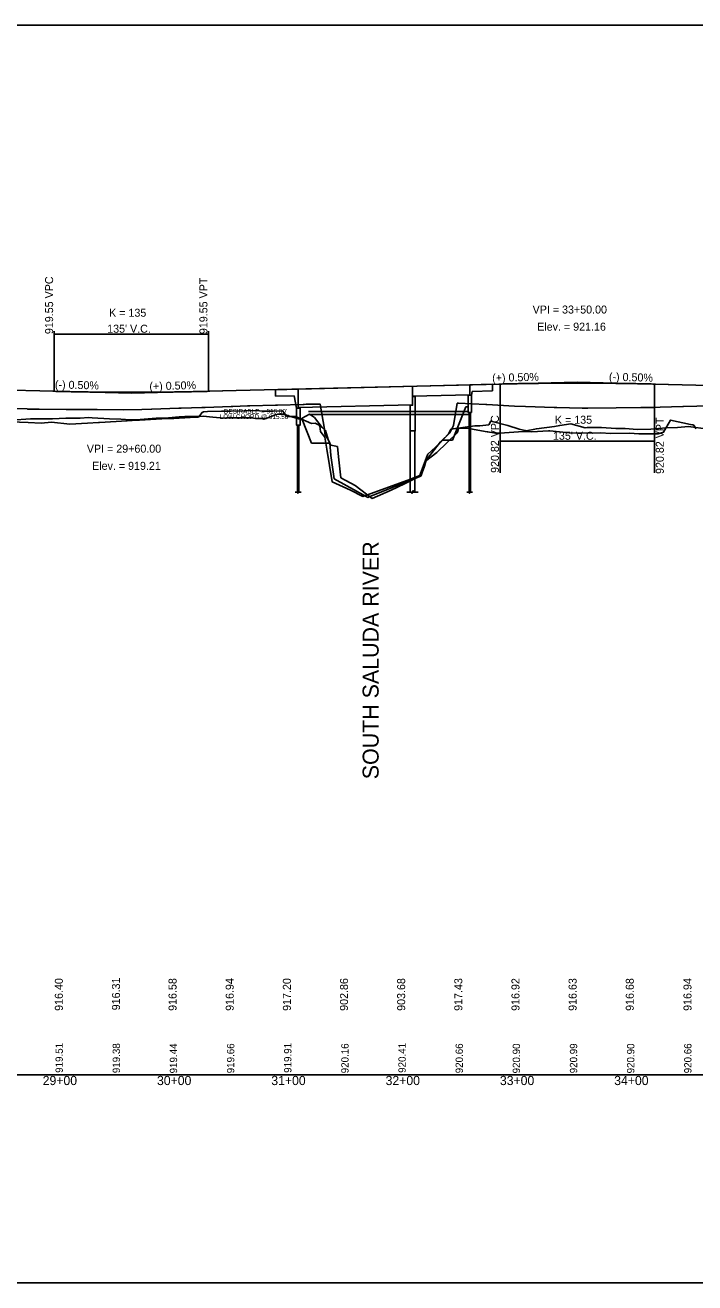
# Model space of a CAD drawing. Extents: x 1538426 to 1542651, y 1162537 to 1163637.
# Drawn here: x 1540293 to 1540879, y 1162537 to 1163637 of the extents above; entities that cross this region are included whole.
import ezdxf

# ---------------------------------------------------------------- set-up
doc = ezdxf.new("R2010")
doc.units = 0
for name, color, linetype in [('BR_CONCRETE', 7, 'Continuous'), ('BR_EXIST_GROUND_LT', 7, 'Continuous'), ('BR_EXIST_GROUND_RT', 7, 'Continuous'), ('BR_GROUND LINES', 7, 'Continuous'), ('BR_USER NOTES', 7, 'Continuous'), ('Default', 7, 'Continuous'), ('RD_DDB_GradeTX', 7, 'Continuous'), ('RD_DDB_Profile_EX', 7, 'Continuous'), ('RD_DDB_Profile_Lbl', 7, 'Continuous'), ('RD_DDB_Profile_PR', 7, 'Continuous'), ('RD_DDB_StaTX', 7, 'Continuous'), ('RD_DDB_StripGrade', 7, 'Continuous'), ('RD_DDB_VCLbl', 7, 'Continuous'), ('RD_HC_Data_Tic', 7, 'Continuous'), ('RD_SHT_ShtClip', 7, 'Continuous'), ('RD_SHT_TX', 7, 'Continuous')]:
    doc.layers.add(name, color=color, linetype=linetype)

msp = doc.modelspace()

# ---------------------------------------------------------------- linework, layer by layer
at = {"layer": 'BR_CONCRETE'}
for p, q in [((1540511.9, 1163317.9), (1540531.9, 1163318.4)), ((1540511.9, 1163312.1), (1540511.9, 1163317.9)), ((1540531.9, 1163318.4), (1540681.9, 1163322.2)), ((1540531.9, 1163301.8), (1540531.9, 1163318.4)), ((1540631.9, 1163320.9), (1540631.9, 1163304.7)), ((1540681.9, 1163322.2), (1540701.9, 1163322.7)), ((1540681.9, 1163322.2), (1540681.9, 1163313)), ((1540683.4, 1163313), (1540684.1, 1163316.4)), ((1540684.1, 1163316.4), (1540701.9, 1163316.8)), ((1540511.9, 1163312.1), (1540528.3, 1163312.5)), ((1540530.4, 1163301.8), (1540528.3, 1163312.5)), ((1540631.9, 1163312.2), (1540681.9, 1163313.4)), ((1540531.9, 1163302.2), (1540631.9, 1163304.7)), ((1540681.3, 1163298), (1540681.3, 1163228.4)), ((1540682.5, 1163298), (1540682.5, 1163228.4)), ((1540531.3, 1163286.8), (1540531.3, 1163228.4)), ((1540532.5, 1163286.8), (1540532.5, 1163228.4)), ((1540629.9, 1163228.4), (1540629.9, 1163281.8)), ((1540633.9, 1163228.4), (1540633.9, 1163281.8))]:
    msp.add_line(p, q, dxfattribs=at)
for points in [[(1540629.7, 1163304.3), (1540631.9, 1163304.3), (1540631.9, 1163311.8), (1540634.2, 1163311.8), (1540634.2, 1163281.8), (1540629.7, 1163281.8)], [(1540683.4, 1163313), (1540680.4, 1163313), (1540680.4, 1163298), (1540683.4, 1163298)], [(1540530.4, 1163301.8), (1540533.4, 1163301.8), (1540533.4, 1163286.8), (1540530.4, 1163286.8)]]:
    msp.add_lwpolyline(points, close=True, dxfattribs=at)
for points in [[(1540529.3, 1163228.4), (1540531.6, 1163228.4), (1540531.6, 1163227.2), (1540532.2, 1163229.6), (1540532.3, 1163228.4), (1540534.4, 1163228.4)], [(1540626.9, 1163228.4), (1540631.3, 1163228.4), (1540631.3, 1163227.2), (1540632.5, 1163229.6), (1540632.5, 1163228.4), (1540636.8, 1163228.4)], [(1540679.3, 1163228.4), (1540681.5, 1163228.4), (1540681.6, 1163227.2), (1540682.1, 1163229.6), (1540682.3, 1163228.4), (1540684.4, 1163228.4)]]:
    msp.add_lwpolyline(points, dxfattribs=at)
at = {"layer": 'BR_EXIST_GROUND_LT'}
msp.add_lwpolyline([(1540280.9, 1163291.3), (1540297.5, 1163292.5), (1540298.7, 1163292.5), (1540311.8, 1163292.3), (1540316.8, 1163292.5), (1540328.6, 1163293.1), (1540341.2, 1163293), (1540348.5, 1163293.5), (1540351.7, 1163293.4), (1540366.8, 1163292.4), (1540376.6, 1163292.1), (1540385, 1163291.5), (1540390.1, 1163291.4), (1540407.7, 1163292.9), (1540415, 1163293.1), (1540427.8, 1163294.3), (1540432.6, 1163294.4), (1540448.8, 1163294.8), (1540457.2, 1163293.9), (1540466.7, 1163293), (1540469.1, 1163293.2), (1540491.5, 1163293.2), (1540494.4, 1163292.7), (1540503.9, 1163292.6), (1540511.8, 1163295.8), (1540515, 1163296.5), (1540518.3, 1163296.6), (1540534.2, 1163291.9), (1540534.6, 1163291.9), (1540535.4, 1163293), (1540541.6, 1163296.4), (1540546, 1163293.6), (1540552.9, 1163284.7), (1540555.8, 1163282.2), (1540558.3, 1163273.4), (1540560.3, 1163269.5), (1540566.1, 1163268.2), (1540567, 1163259.1), (1540569.2, 1163240.9), (1540581.8, 1163234.1), (1540596.6, 1163222.8), (1540613.3, 1163230), (1540624.9, 1163235.7), (1540639.4, 1163242.7), (1540643.3, 1163255.3), (1540653, 1163263.1), (1540670.9, 1163280.2), (1540671.4, 1163281.4), (1540672.1, 1163284), (1540679.5, 1163284.3), (1540697, 1163281.1), (1540697.5, 1163281.1), (1540704.6, 1163279.8), (1540708.3, 1163279.8), (1540728.6, 1163281.2), (1540736.1, 1163281.1), (1540750.7, 1163282), (1540752, 1163282), (1540769, 1163280.2), (1540776.9, 1163280), (1540778.5, 1163279.8), (1540779.9, 1163279.8), (1540796.5, 1163280.2), (1540804.9, 1163279.5), (1540821.8, 1163279.9), (1540829.8, 1163279.3), (1540831.7, 1163279.3), (1540846.7, 1163279.3), (1540851.5, 1163280.6), (1540857.5, 1163291.3), (1540875, 1163287.5), (1540877.2, 1163287.3), (1540878.1, 1163286.7), (1540879.7, 1163283.6)], dxfattribs=at)
at = {"layer": 'BR_EXIST_GROUND_RT'}
msp.add_lwpolyline([(1540280.3, 1163289.7), (1540295.7, 1163289.1), (1540306.9, 1163288.6), (1540316.1, 1163289.6), (1540332.1, 1163287.8), (1540347.4, 1163288.7), (1540357.1, 1163289.3), (1540358, 1163289.3), (1540382.1, 1163290.7), (1540391.1, 1163291.3), (1540392.9, 1163291.3), (1540412.4, 1163292.3), (1540417.9, 1163292.6), (1540423, 1163292.8), (1540442.3, 1163293.8), (1540444.5, 1163293.9), (1540447.7, 1163298), (1540449, 1163298.6), (1540452.5, 1163298.8), (1540464.6, 1163299), (1540465.8, 1163299), (1540473.2, 1163299.2), (1540495.5, 1163299.7), (1540500.3, 1163299.1), (1540509.9, 1163299.1), (1540518, 1163299.5), (1540519.6, 1163297.8), (1540522, 1163294.5), (1540529.4, 1163294.5), (1540543.4, 1163288.4), (1540546.6, 1163288.7), (1540550.3, 1163286.9), (1540550.8, 1163286), (1540551.2, 1163281.4), (1540551.8, 1163280.5), (1540555.2, 1163276.3), (1540556.8, 1163266), (1540561.6, 1163237.2), (1540577.6, 1163230.1), (1540588.5, 1163224.6), (1540627.7, 1163238.9), (1540638.2, 1163242.8), (1540638.7, 1163244.7), (1540644.8, 1163261), (1540645.3, 1163261.4), (1540655.4, 1163270.8), (1540663.4, 1163279.4), (1540664.6, 1163281.6), (1540665.4, 1163283.3), (1540686.4, 1163286.2), (1540690.7, 1163286.2), (1540698.6, 1163287.1), (1540700.3, 1163290.4), (1540715.1, 1163286.6), (1540725, 1163283.5), (1540730.3, 1163282.2), (1540731.4, 1163281.8), (1540740.3, 1163283.7), (1540756, 1163285.6), (1540760.6, 1163286.7), (1540770.2, 1163287.9), (1540782.8, 1163284.6), (1540784.6, 1163284.7), (1540797.2, 1163284.9), (1540809.7, 1163283.9), (1540818, 1163284), (1540828.4, 1163283.2), (1540840.3, 1163283.3), (1540853.6, 1163284.5), (1540863.7, 1163284.7), (1540873.3, 1163285.6), (1540890.5, 1163283.5)], dxfattribs=at)
at = {"layer": 'BR_GROUND LINES'}
for p, q in [((1540678.4, 1163303), (1540666.7, 1163273.7)), ((1540666.7, 1163273.7), (1540678.4, 1163303)), ((1540680.4, 1163303), (1540678.4, 1163303)), ((1540678.4, 1163303), (1540680.4, 1163303)), ((1540533.4, 1163291.8), (1540535.4, 1163291.8)), ((1540533.4, 1163291.7), (1540535.4, 1163291.8)), ((1540535.4, 1163291.8), (1540543.6, 1163271.2)), ((1540535.4, 1163291.8), (1540543.6, 1163271.2)), ((1540666.7, 1163273.7), (1540657.7, 1163273.7)), ((1540543.6, 1163271.2), (1540559.6, 1163271.2))]:
    msp.add_line(p, q, dxfattribs=at)
at = {"layer": 'BR_USER NOTES'}
for p, q in [((1540540.9, 1163298.7), (1540680.9, 1163298.7)), ((1540540.9, 1163296.2), (1540680.9, 1163296.2))]:
    msp.add_line(p, q, dxfattribs=at)
at = {"layer": 'Default'}
msp.add_line((1540701.9, 1163322.7), (1540701.9, 1163316.8), dxfattribs=at)
at = {"layer": 'RD_DDB_GradeTX'}
for p, q in [((1540305.9, 1163316.8), (1540385.9, 1163314.8)), ((1540465.9, 1163316.8), (1540385.9, 1163314.8)), ((1540695.9, 1163322.5), (1540775.9, 1163324.5)), ((1540855.9, 1163322.5), (1540775.9, 1163324.5))]:
    msp.add_line(p, q, dxfattribs=at)
at = {"layer": 'RD_DDB_Profile_EX'}
msp.add_lwpolyline([(1540270.5, 1163301.5), (1540294.6, 1163301.1), (1540295.1, 1163301), (1540303.7, 1163300.9), (1540305.3, 1163300.9), (1540328.7, 1163300.7), (1540329.6, 1163300.7), (1540353.8, 1163300.5), (1540356, 1163300.5), (1540378.8, 1163300.2), (1540395.1, 1163300.7), (1540403.4, 1163301), (1540403.8, 1163301), (1540427.4, 1163301.7), (1540428.8, 1163301.7), (1540429.4, 1163301.7), (1540447.5, 1163302.2), (1540448.2, 1163302.3), (1540450.4, 1163302.3), (1540473.2, 1163303.3), (1540474.5, 1163303.3), (1540487.5, 1163303.9), (1540489.5, 1163303.9), (1540512, 1163304.4), (1540513.7, 1163304.5), (1540536.3, 1163304.9), (1540537, 1163305), (1540538.8, 1163305.1), (1540551, 1163305.3), (1540554.8, 1163283.5), (1540555.1, 1163279.2), (1540556.1, 1163277.7), (1540559.6, 1163271.4), (1540560.5, 1163260.4), (1540563.3, 1163240), (1540591.3, 1163224.5), (1540592.2, 1163224), (1540592.6, 1163223.7), (1540594.4, 1163224.5), (1540639.1, 1163242.4), (1540642.4, 1163251.1), (1540643.9, 1163256.4), (1540656.2, 1163272.3), (1540664.4, 1163280.1), (1540667.8, 1163286.7), (1540670.9, 1163306.1), (1540672, 1163306.1), (1540695.9, 1163304.9), (1540696.8, 1163304.8), (1540721.1, 1163303.6), (1540730.7, 1163303.1), (1540755.7, 1163302.4), (1540758.2, 1163302.3), (1540780.3, 1163301.7), (1540780.7, 1163301.7), (1540785.1, 1163301.6), (1540810.1, 1163301.9), (1540831.5, 1163302.2), (1540835.1, 1163302.3), (1540843.9, 1163302.4), (1540848.4, 1163302.5), (1540868.3, 1163303.2), (1540868.9, 1163303.2), (1540892.3, 1163303.9)], dxfattribs=at)
at = {"layer": 'RD_DDB_Profile_PR'}
for p, q in [((1540203.4, 1163319.3), (1540318.4, 1163316.5)), ((1540453.4, 1163316.5), (1540708.4, 1163322.8)), ((1540843.4, 1163322.8), (1541058.4, 1163317.5))]:
    msp.add_line(p, q, dxfattribs=at)
for points in [[(1540318.4, 1163316.5), (1540321.1, 1163316.4), (1540323.8, 1163316.3), (1540326.5, 1163316.3), (1540329.2, 1163316.2), (1540331.9, 1163316.2), (1540334.6, 1163316.1), (1540337.3, 1163316.1), (1540340, 1163316), (1540342.7, 1163316), (1540345.4, 1163315.9), (1540348.1, 1163315.9), (1540350.8, 1163315.8), (1540353.5, 1163315.8), (1540356.2, 1163315.8), (1540358.9, 1163315.7), (1540361.6, 1163315.7), (1540364.3, 1163315.7), (1540367, 1163315.7), (1540369.7, 1163315.7), (1540372.4, 1163315.6), (1540375.1, 1163315.6), (1540377.8, 1163315.6), (1540380.5, 1163315.6), (1540383.2, 1163315.6), (1540385.9, 1163315.6), (1540388.6, 1163315.6), (1540391.3, 1163315.6), (1540394, 1163315.6), (1540396.7, 1163315.6), (1540399.4, 1163315.6), (1540402.1, 1163315.7), (1540404.8, 1163315.7), (1540407.5, 1163315.7), (1540410.2, 1163315.7), (1540412.9, 1163315.7), (1540415.6, 1163315.8), (1540418.3, 1163315.8), (1540421, 1163315.8), (1540423.7, 1163315.9), (1540426.4, 1163315.9), (1540429.1, 1163316), (1540431.8, 1163316), (1540434.5, 1163316.1), (1540437.2, 1163316.1), (1540439.9, 1163316.2), (1540442.6, 1163316.2), (1540445.3, 1163316.3), (1540448, 1163316.3), (1540450.7, 1163316.4), (1540453.4, 1163316.5)], [(1540708.4, 1163322.8), (1540711.1, 1163322.9), (1540713.8, 1163323), (1540716.5, 1163323), (1540719.2, 1163323.1), (1540721.9, 1163323.1), (1540724.6, 1163323.2), (1540727.3, 1163323.2), (1540730, 1163323.3), (1540732.7, 1163323.3), (1540735.4, 1163323.4), (1540738.1, 1163323.4), (1540740.8, 1163323.4), (1540743.5, 1163323.5), (1540746.2, 1163323.5), (1540748.9, 1163323.5), (1540751.6, 1163323.6), (1540754.3, 1163323.6), (1540757, 1163323.6), (1540759.7, 1163323.6), (1540762.4, 1163323.6), (1540765.1, 1163323.7), (1540767.8, 1163323.7), (1540770.5, 1163323.7), (1540773.2, 1163323.7), (1540775.9, 1163323.7), (1540778.6, 1163323.7), (1540781.3, 1163323.7), (1540784, 1163323.7), (1540786.7, 1163323.7), (1540789.4, 1163323.6), (1540792.1, 1163323.6), (1540794.8, 1163323.6), (1540797.5, 1163323.6), (1540800.2, 1163323.6), (1540802.9, 1163323.5), (1540805.6, 1163323.5), (1540808.3, 1163323.5), (1540811, 1163323.4), (1540813.7, 1163323.4), (1540816.4, 1163323.4), (1540819.1, 1163323.3), (1540821.8, 1163323.3), (1540824.5, 1163323.2), (1540827.2, 1163323.2), (1540829.9, 1163323.1), (1540832.6, 1163323.1), (1540835.3, 1163323), (1540838, 1163323), (1540840.7, 1163322.9), (1540843.4, 1163322.8)]]:
    msp.add_spline(points, degree=3, dxfattribs=at)
at = {"layer": 'RD_DDB_VCLbl'}
for p, q in [((1540318.4, 1163369), (1540318.4, 1163316.5)), ((1540318.4, 1163366.5), (1540453.4, 1163366.5)), ((1540453.4, 1163369), (1540453.4, 1163316.5)), ((1540708.4, 1163245.2), (1540708.4, 1163322.8)), ((1540843.4, 1163245.2), (1540843.4, 1163322.8)), ((1540708.4, 1163272.8), (1540843.4, 1163272.8))]:
    msp.add_line(p, q, dxfattribs=at)
at = {"layer": 'RD_HC_Data_Tic'}
msp.add_line((1538425.9, 1162718.7), (1542651.1, 1162718.7), dxfattribs=at)
at = {"layer": 'RD_SHT_ShtClip'}
for p, q in [((1539559.8, 1163636.7), (1541409.8, 1163636.7)), ((1541409.8, 1162536.7), (1539559.8, 1162536.7))]:
    msp.add_line(p, q, dxfattribs=at)

# ---------------------------------------------------------------- texts
at = {"layer": 'BR_USER NOTES'}
for s, p in [("LOW CHORD @ 915.50'", (1540463.2, 1163292.3)), ("DESIRABLE = 916.00'", (1540466.8, 1163297))]:
    msp.add_text(s, height=4, dxfattribs=at).set_placement(p)
at = {"layer": 'RD_DDB_GradeTX'}
for s, rotation, p in [('(+) 0.50%', 1.4321, (1540701.6, 1163324.7)), ('(-) 0.50%', 358.5679, (1540803.6, 1163325.8)), ('(-) 0.50%', 358.5679, (1540318.9, 1163319)), ('(+) 0.50%', 1.4321, (1540401.7, 1163317.4))]:
    msp.add_text(s, height=7, rotation=rotation, dxfattribs=at).set_placement(p)
at = {"layer": 'RD_DDB_Profile_Lbl'}
for s, p in [('VPI = 33+50.00', (1540736.9, 1163384.5)), ('Elev. = 921.16', (1540740.9, 1163369.5)), ('VPI = 29+60.00', (1540346.9, 1163262.8)), ('Elev. = 919.21', (1540351.5, 1163247.8))]:
    msp.add_text(s, height=7, dxfattribs=at).set_placement(p)
at = {"layer": 'RD_DDB_StaTX'}
for s, p in [('29+00', (1540308.3, 1162709.7)), ('30+00', (1540408.3, 1162709.7)), ('31+00', (1540508.3, 1162709.7)), ('32+00', (1540608.3, 1162709.7)), ('33+00', (1540708.3, 1162709.7)), ('34+00', (1540808.3, 1162709.7))]:
    msp.add_text(s, height=8, dxfattribs=at).set_placement(p)
at = {"layer": 'RD_DDB_StripGrade'}
for s, height, p in [('919.55 VPC', 7, (1540317.4, 1163366.5)), ('919.55 VPT', 7, (1540452.4, 1163366.5)), ('920.82 VPC', 7, (1540707.4, 1163245.1)), ('920.82 VPT', 7, (1540851.7, 1163244.2)), ('916.40', 7, (1540325.9, 1162774.6)), ('916.31', 7, (1540375.9, 1162775.1)), ('916.58', 7, (1540425.4, 1162774.6)), ('916.94', 7, (1540475.4, 1162774.6)), ('917.20', 7, (1540525.4, 1162774.6)), ('902.86', 7, (1540575.4, 1162774.6)), ('903.68', 7, (1540625.4, 1162774.6)), ('917.43', 7, (1540675.4, 1162774.6)), ('916.92', 7, (1540725.4, 1162774.6)), ('916.63', 7, (1540775.4, 1162774.6)), ('916.68', 7, (1540825.4, 1162774.6)), ('916.94', 7, (1540875.9, 1162774.6)), ('919.51', 6.4, (1540325.9, 1162720.4)), ('919.38', 6.4, (1540375.9, 1162720.1)), ('919.44', 6.4, (1540425.9, 1162719.9)), ('919.66', 6.4, (1540475.9, 1162720)), ('919.91', 6.4, (1540525.9, 1162720.4)), ('920.16', 6.4, (1540575.9, 1162720)), ('920.41', 6.4, (1540625.9, 1162720.4)), ('920.66', 6.4, (1540675.9, 1162720)), ('920.90', 6.4, (1540725.9, 1162719.9)), ('920.99', 6.4, (1540775.9, 1162720)), ('920.90', 6.4, (1540825.9, 1162719.9)), ('920.66', 6.4, (1540875.9, 1162720))]:
    msp.add_text(s, height=height, rotation=90, dxfattribs=at).set_placement(p)
at = {"layer": 'RD_DDB_VCLbl'}
for s, p in [('K = 135', (1540366.4, 1163381.7)), ("135' V.C.", (1540364.7, 1163367.7)), ('K = 135', (1540756.4, 1163288.1)), ("135' V.C.", (1540754.7, 1163274.1))]:
    msp.add_text(s, height=7, dxfattribs=at).set_placement(p)
at = {"layer": 'RD_SHT_TX'}
msp.add_text('SOUTH SALUDA RIVER', height=14, rotation=90, dxfattribs=at).set_placement((1540602.2, 1162977.2))

doc.saveas('drawing.dxf')
